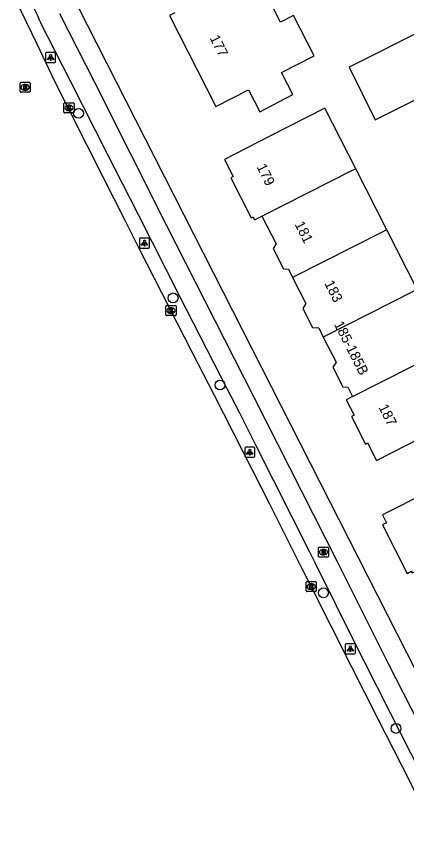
# Model space of a CAD drawing. Extents: x 162347 to 162868, y 381221 to 381813.
# Drawn here: x 162358.7 to 162397.4, y 381573.3 to 381653.9 of the extents above; entities that cross this region are included whole.
import ezdxf

# ---------------------------------------------------------------- set-up
doc = ezdxf.new("R2010")
doc.units = 0
for name, color, linetype in [('IMGEO_Boom', 7, 'Continuous'), ('IMGEO_Brandkraan', 7, 'Continuous'), ('IMGEO_Fietspad_open', 7, 'Continuous'), ('IMGEO_Kolk', 7, 'Continuous'), ('IMGEO_Lichtpunt', 7, 'Continuous'), ('IMGEO_Pand', 7, 'Continuous'), ('IMGEO_Pand_nummerreeks', 7, 'Continuous'), ('IMGEO_Rijbaan_regionaal_gesloten', 7, 'Continuous'), ('IMGEO_Rioolput', 7, 'Continuous'), ('IMGEO_Voetpad_open', 7, 'Continuous')]:
    doc.layers.add(name, color=color, linetype=linetype)

msp = doc.modelspace()

# ---------------------------------------------------------------- linework, layer by layer
at = {"layer": 'IMGEO_Boom'}
for centre in [(162364.839, 381644.26), (162374.24, 381625.935), (162378.89, 381617.287), (162389.173, 381596.654), (162396.379, 381583.19)]:
    msp.add_circle(centre, 0.489, dxfattribs=at)
at = {"layer": 'IMGEO_Brandkraan'}
for p, q in [((162388.675, 381600.263), (162388.675, 381601.115)), ((162388.75, 381601.189), (162389.602, 381601.189)), ((162389.163, 381600.969), (162389.188, 381600.969)), ((162389.676, 381601.115), (162389.676, 381600.263)), ((162389.602, 381600.189), (162388.75, 381600.189)), ((162389.186, 381600.409), (162389.161, 381600.409))]:
    msp.add_line(p, q, dxfattribs=at)
for points in [[(162388.675, 381600.263), (162388.675, 381601.115)], [(162388.75, 381601.189), (162389.602, 381601.189)], [(162389.023, 381600.889), (162389.023, 381600.489), (162389.236, 381600.489)], [(162389.254, 381600.889), (162389.023, 381600.889)], [(162389.202, 381600.808), (162389.148, 381600.808), (162389.148, 381600.732)], [(162389.676, 381601.115), (162389.676, 381600.263)], [(162389.602, 381600.189), (162388.75, 381600.189)], [(162389.148, 381600.732), (162389.201, 381600.732)], [(162389.21, 381600.656), (162389.148, 381600.656), (162389.148, 381600.575)], [(162389.148, 381600.575), (162389.21, 381600.575)]]:
    msp.add_lwpolyline(points, dxfattribs=at)
for centre, radius, start, end in [((162388.752, 381601.113), 0.0765, 91.55205, 178.44795), ((162388.752, 381601.113), 0.0765, 91.55205, 178.44795), ((162389.203, 381600.77), 0.0379, 267.82845, 90.93552), ((162389.258, 381600.744), 0.145, 59.4692, 91.53667), ((162389.283, 381600.791), 0.0922, 285.51372, 58.15012), ((162389.6, 381601.113), 0.0765, 1.55205, 88.44795), ((162389.6, 381601.113), 0.0765, 1.55205, 88.44795), ((162388.752, 381600.265), 0.0765, 181.55205, 268.44795), ((162388.752, 381600.265), 0.0765, 181.55205, 268.44795), ((162389.211, 381600.615), 0.0404, 269.87594, 90.50774), ((162389.242, 381600.74), 0.251, 268.66757, 293.53466), ((162389.288, 381600.599), 0.105, 301.31148, 78.98903), ((162389.6, 381600.265), 0.0765, 271.55205, 358.44795), ((162389.6, 381600.265), 0.0765, 271.55205, 358.44795)]:
    msp.add_arc(centre, radius, start, end, dxfattribs=at)
for centre, major_axis, ratio, start_param, end_param in [((162389.162, 381600.689), (-0.387, 0.002), 0.722429, 4.712389, 7.853982), ((162389.187, 381600.689), (-0.39, 0.002), 0.717154, 1.570796, 4.712389)]:
    msp.add_ellipse(centre, major_axis=major_axis, ratio=ratio, start_param=start_param, end_param=end_param, dxfattribs=at)
at = {"layer": 'IMGEO_Fietspad_open'}
for points in [[(162362.948, 381654.184), (162366.42, 381647.346), (162373.547, 381633.19), (162382.229, 381616.136), (162390.519, 381599.747), (162395.607, 381589.625), (162403.109, 381574.937), (162411.637, 381558.14), (162419.849, 381541.928), (162427.81, 381526.456), (162437.491, 381507.399), (162441.265, 381500), (162456.812, 381469.521), (162464.953, 381453.521)], [(162410.306, 381556.355), (162407.33, 381562.188), (162400.899, 381574.731), (162395.837, 381584.693), (162393.201, 381589.881), (162392.517, 381591.227), (162388.339, 381599.637), (162387.808, 381600.705), (162382.464, 381611.316), (162380.864, 381614.494), (162379.579, 381616.989), (162374.942, 381625.996), (162370.754, 381634.243), (162367.724, 381640.204), (162364.002, 381647.524), (162361.111, 381653.216)]]:
    msp.add_lwpolyline(points, dxfattribs=at)
msp.add_arc((162395.374, 381669.964), 38.137, 197.00448, 206.04996, dxfattribs=at)
at = {"layer": 'IMGEO_Kolk'}
for p, q in [((162363.394, 381644.371), (162363.394, 381645.223)), ((162363.469, 381645.297), (162364.321, 381645.297)), ((162364.395, 381645.223), (162364.395, 381644.371)), ((162364.321, 381644.297), (162363.469, 381644.297)), ((162363.905, 381644.517), (162363.88, 381644.517)), ((162363.882, 381645.077), (162363.907, 381645.077)), ((162373.529, 381624.247), (162373.529, 381625.099)), ((162373.604, 381625.173), (162374.456, 381625.173)), ((162374.017, 381624.953), (162374.042, 381624.953)), ((162374.53, 381625.099), (162374.53, 381624.247)), ((162374.456, 381624.173), (162373.604, 381624.173)), ((162374.04, 381624.393), (162374.015, 381624.393)), ((162387.453, 381596.844), (162387.453, 381597.696)), ((162387.528, 381597.77), (162388.38, 381597.77)), ((162388.454, 381597.696), (162388.454, 381596.844)), ((162388.38, 381596.77), (162387.528, 381596.77)), ((162387.964, 381596.99), (162387.939, 381596.99)), ((162387.941, 381597.55), (162387.966, 381597.55))]:
    msp.add_line(p, q, dxfattribs=at)
for points in [[(162363.394, 381644.371), (162363.394, 381645.223)], [(162363.469, 381645.297), (162364.321, 381645.297)], [(162364.395, 381645.223), (162364.395, 381644.371)], [(162364.321, 381644.297), (162363.469, 381644.297)], [(162363.715, 381644.997), (162363.838, 381644.997), (162363.838, 381644.846), (162363.968, 381644.997), (162364.132, 381644.997), (162363.986, 381644.846), (162364.139, 381644.597), (162363.987, 381644.597), (162363.902, 381644.761), (162363.838, 381644.694), (162363.838, 381644.597), (162363.715, 381644.597), (162363.715, 381644.997)], [(162373.529, 381624.247), (162373.529, 381625.099)], [(162373.604, 381625.173), (162374.456, 381625.173)], [(162374.53, 381625.099), (162374.53, 381624.247)], [(162374.456, 381624.173), (162373.604, 381624.173)], [(162373.85, 381624.873), (162373.973, 381624.873), (162373.973, 381624.722), (162374.103, 381624.873), (162374.267, 381624.873), (162374.121, 381624.722), (162374.274, 381624.473), (162374.122, 381624.473), (162374.037, 381624.637), (162373.973, 381624.57), (162373.973, 381624.473), (162373.85, 381624.473), (162373.85, 381624.873)], [(162387.453, 381596.844), (162387.453, 381597.696)], [(162387.528, 381597.77), (162388.38, 381597.77)], [(162388.454, 381597.696), (162388.454, 381596.844)], [(162388.38, 381596.77), (162387.528, 381596.77)], [(162387.774, 381597.47), (162387.897, 381597.47), (162387.897, 381597.319), (162388.027, 381597.47), (162388.191, 381597.47), (162388.045, 381597.319), (162388.198, 381597.07), (162388.046, 381597.07), (162387.961, 381597.234), (162387.897, 381597.167), (162387.897, 381597.07), (162387.774, 381597.07), (162387.774, 381597.47)]]:
    msp.add_lwpolyline(points, dxfattribs=at)
for centre, start, end in [((162363.471, 381645.221), 91.55205, 178.44795), ((162363.471, 381645.221), 91.55205, 178.44795), ((162364.319, 381645.221), 1.55205, 88.44795), ((162364.319, 381645.221), 1.55205, 88.44795), ((162363.471, 381644.373), 181.55205, 268.44795), ((162363.471, 381644.373), 181.55205, 268.44795), ((162364.319, 381644.373), 271.55205, 358.44795), ((162364.319, 381644.373), 271.55205, 358.44795), ((162373.606, 381625.097), 91.55205, 178.44795), ((162373.606, 381625.097), 91.55205, 178.44795), ((162374.454, 381625.097), 1.55205, 88.44795), ((162374.454, 381625.097), 1.55205, 88.44795), ((162373.606, 381624.249), 181.55205, 268.44795), ((162373.606, 381624.249), 181.55205, 268.44795), ((162374.454, 381624.249), 271.55205, 358.44795), ((162374.454, 381624.249), 271.55205, 358.44795), ((162387.53, 381597.694), 91.55205, 178.44795), ((162387.53, 381597.694), 91.55205, 178.44795), ((162388.378, 381597.694), 1.55205, 88.44795), ((162388.378, 381597.694), 1.55205, 88.44795), ((162387.53, 381596.846), 181.55205, 268.44795), ((162387.53, 381596.846), 181.55205, 268.44795), ((162388.378, 381596.846), 271.55205, 358.44795), ((162388.378, 381596.846), 271.55205, 358.44795)]:
    msp.add_arc(centre, 0.0765, start, end, dxfattribs=at)
for centre, major_axis, ratio, start_param, end_param in [((162363.881, 381644.797), (-0.387, 0.002), 0.722429, 4.712389, 7.853982), ((162363.906, 381644.797), (-0.39, 0.002), 0.717154, 1.570796, 4.712389), ((162374.016, 381624.673), (-0.387, 0.002), 0.722429, 4.712389, 7.853982), ((162374.041, 381624.673), (-0.39, 0.002), 0.717154, 1.570796, 4.712389), ((162387.94, 381597.27), (-0.387, 0.002), 0.722429, 4.712389, 7.853982), ((162387.965, 381597.27), (-0.39, 0.002), 0.717154, 1.570796, 4.712389)]:
    msp.add_ellipse(centre, major_axis=major_axis, ratio=ratio, start_param=start_param, end_param=end_param, dxfattribs=at)
at = {"layer": 'IMGEO_Lichtpunt'}
for p, q in [((162361.573, 381650.212), (162361.573, 381649.405)), ((162361.573, 381650.212), (162361.573, 381649.405)), ((162362.475, 381650.307), (162361.667, 381650.307)), ((162362.475, 381650.307), (162361.667, 381650.307)), ((162362.569, 381649.405), (162362.569, 381650.212)), ((162362.569, 381649.405), (162362.569, 381650.212)), ((162361.667, 381649.311), (162362.475, 381649.311)), ((162361.667, 381649.311), (162362.475, 381649.311)), ((162370.892, 381631.786), (162370.892, 381630.979)), ((162370.892, 381631.786), (162370.892, 381630.979)), ((162371.794, 381631.881), (162370.986, 381631.881)), ((162371.794, 381631.881), (162370.986, 381631.881)), ((162371.888, 381630.979), (162371.888, 381631.786)), ((162371.888, 381630.979), (162371.888, 381631.786)), ((162370.986, 381630.885), (162371.794, 381630.885)), ((162370.986, 381630.885), (162371.794, 381630.885)), ((162381.356, 381611.024), (162381.356, 381610.217)), ((162381.356, 381611.024), (162381.356, 381610.217)), ((162382.258, 381611.119), (162381.45, 381611.119)), ((162382.258, 381611.119), (162381.45, 381611.119)), ((162382.352, 381610.217), (162382.352, 381611.024)), ((162382.352, 381610.217), (162382.352, 381611.024)), ((162381.45, 381610.123), (162382.258, 381610.123)), ((162381.45, 381610.123), (162382.258, 381610.123)), ((162391.346, 381591.494), (162391.346, 381590.687)), ((162391.346, 381591.494), (162391.346, 381590.687)), ((162392.248, 381591.589), (162391.44, 381591.589)), ((162392.248, 381591.589), (162391.44, 381591.589)), ((162392.342, 381590.687), (162392.342, 381591.494)), ((162392.342, 381590.687), (162392.342, 381591.494)), ((162391.44, 381590.593), (162392.248, 381590.593)), ((162391.44, 381590.593), (162392.248, 381590.593))]:
    msp.add_line(p, q, dxfattribs=at)
for points in [[(162361.947, 381649.876), (162361.986, 381649.848), (162361.798, 381649.586), (162361.76, 381649.613), (162361.947, 381649.876)], [(162362.049, 381649.828), (162362.096, 381649.828), (162362.096, 381649.506), (162362.049, 381649.506), (162362.049, 381649.828)], [(162362.159, 381649.848), (162362.197, 381649.875), (162362.384, 381649.613), (162362.345, 381649.585), (162362.159, 381649.848)], [(162371.266, 381631.45), (162371.305, 381631.422), (162371.117, 381631.16), (162371.079, 381631.187), (162371.266, 381631.45)], [(162371.368, 381631.402), (162371.415, 381631.402), (162371.415, 381631.08), (162371.368, 381631.08), (162371.368, 381631.402)], [(162371.478, 381631.422), (162371.516, 381631.449), (162371.703, 381631.187), (162371.664, 381631.159), (162371.478, 381631.422)], [(162381.73, 381610.688), (162381.769, 381610.66), (162381.581, 381610.398), (162381.543, 381610.425), (162381.73, 381610.688)], [(162381.832, 381610.64), (162381.879, 381610.64), (162381.879, 381610.318), (162381.832, 381610.318), (162381.832, 381610.64)], [(162381.942, 381610.66), (162381.98, 381610.687), (162382.167, 381610.425), (162382.128, 381610.397), (162381.942, 381610.66)], [(162391.72, 381591.158), (162391.759, 381591.13), (162391.571, 381590.868), (162391.533, 381590.895), (162391.72, 381591.158)], [(162391.822, 381591.11), (162391.869, 381591.11), (162391.869, 381590.788), (162391.822, 381590.788), (162391.822, 381591.11)], [(162391.932, 381591.13), (162391.97, 381591.157), (162392.157, 381590.895), (162392.118, 381590.867), (162391.932, 381591.13)]]:
    msp.add_lwpolyline(points, dxfattribs=at)
for centre in [(162362.072, 381650.01), (162371.391, 381631.584), (162381.855, 381610.822), (162391.845, 381591.292)]:
    msp.add_circle(centre, 0.0994, dxfattribs=at)
for centre, start, end in [((162361.667, 381650.212), 90, 180), ((162361.667, 381650.212), 90, 180), ((162362.475, 381650.212), 0, 90), ((162362.475, 381650.212), 0, 90), ((162361.667, 381649.405), 180, 270), ((162361.667, 381649.405), 180, 270), ((162362.475, 381649.405), 270, 0), ((162362.475, 381649.405), 270, 360), ((162370.986, 381631.786), 90, 180), ((162370.986, 381631.786), 90, 180), ((162371.794, 381631.786), 0, 90), ((162371.794, 381631.786), 0, 90), ((162370.986, 381630.979), 180, 270), ((162370.986, 381630.979), 180, 270), ((162371.794, 381630.979), 270, 0), ((162371.794, 381630.979), 270, 360), ((162381.45, 381611.024), 90, 180), ((162381.45, 381611.024), 90, 180), ((162382.258, 381611.024), 0, 90), ((162382.258, 381611.024), 0, 90), ((162381.45, 381610.217), 180, 270), ((162381.45, 381610.217), 180, 270), ((162382.258, 381610.217), 270, 0), ((162382.258, 381610.217), 270, 360), ((162391.44, 381591.494), 90, 180), ((162391.44, 381591.494), 90, 180), ((162392.248, 381591.494), 0, 90), ((162392.248, 381591.494), 0, 90), ((162391.44, 381590.687), 180, 270), ((162391.44, 381590.687), 180, 270), ((162392.248, 381590.687), 270, 0), ((162392.248, 381590.687), 270, 360)]:
    msp.add_arc(centre, 0.0946, start, end, dxfattribs=at)
at = {"layer": 'IMGEO_Pand'}
for points in [[(162374.408, 381654.239), (162373.886, 381653.972), (162378.488, 381644.927), (162381.742, 381646.582), (162382.855, 381644.417), (162386.146, 381646.123), (162385.019, 381648.298), (162388.244, 381649.97), (162386.203, 381653.979), (162384.898, 381653.315), (162384.079, 381654.925), (162388.651, 381657.252), (162387.852, 381658.821), (162386.481, 381661.514), (162384.132, 381660.319)], [(162399.713, 381652.851), (162391.711, 381648.827), (162394.326, 381643.627), (162402.34, 381647.657)], [(162392.382, 381638.757), (162389.324, 381644.767), (162383.789, 381641.951), (162379.332, 381639.684), (162380.199, 381637.98), (162379.965, 381637.861), (162381.993, 381633.874), (162382.175, 381633.967), (162382.323, 381633.676), (162383.063, 381634.048)], [(162383.063, 381634.048), (162392.066, 381638.601), (162392.382, 381638.757)], [(162395.465, 381632.697), (162392.382, 381638.757)], [(162383.063, 381634.048), (162384.46, 381631.302), (162384.164, 381630.847), (162385.199, 381628.813), (162385.688, 381628.787), (162386.11, 381627.958)], [(162395.465, 381632.697), (162395.139, 381632.524), (162386.11, 381627.958)], [(162398.481, 381626.77), (162395.465, 381632.697)], [(162386.11, 381627.958), (162387.426, 381625.372), (162387.118, 381624.899), (162388.095, 381622.98), (162388.7, 381622.947), (162389.157, 381622.048)], [(162398.481, 381626.77), (162398.14, 381626.591), (162389.157, 381622.048)], [(162389.157, 381622.048), (162390.426, 381619.555), (162390.098, 381619.05), (162391.087, 381617.106), (162391.598, 381617.079), (162392.072, 381616.147)], [(162392.072, 381616.147), (162391.431, 381615.821), (162392.214, 381614.28), (162391.947, 381614.144), (162393.333, 381611.419), (162393.56, 381611.534), (162394.445, 381609.794), (162398.902, 381612.062), (162404.512, 381614.916), (162401.468, 381620.899)], [(162392.072, 381616.147), (162401.111, 381620.715), (162401.468, 381620.899)], [(162408.169, 381603.815), (162408.091, 381603.968), (162407.93, 381604.285), (162406.673, 381606.755), (162409.231, 381608.056), (162407.798, 381610.873), (162399.497, 381606.65), (162395.04, 381604.382), (162395.432, 381603.613), (162395.031, 381603.409), (162397.484, 381598.588), (162397.885, 381598.792), (162397.971, 381598.622), (162398.225, 381598.75)]]:
    msp.add_lwpolyline(points, dxfattribs=at)
at = {"layer": 'IMGEO_Rijbaan_regionaal_gesloten'}
msp.add_lwpolyline([(162409.049, 381555.709), (162408.71, 381556.396), (162406.049, 381561.587), (162402.557, 381568.4), (162396.915, 381579.56), (162394.619, 381584.098), (162391.996, 381589.28), (162387.783, 381597.606), (162387.066, 381599.034), (162383.842, 381605.454), (162381.2, 381610.636), (162378.309, 381616.304), (162376.144, 381620.551), (162370.915, 381630.775), (162369.471, 381633.629), (162367.291, 381637.935), (162362.48, 381647.434), (162360.733, 381651.139), (162358.654, 381655.431)], dxfattribs=at)
at = {"layer": 'IMGEO_Rioolput'}
for p, q in [((162359.041, 381646.419), (162359.041, 381647.271)), ((162359.116, 381647.345), (162359.968, 381647.345)), ((162359.529, 381647.125), (162359.554, 381647.125)), ((162360.042, 381647.271), (162360.042, 381646.419)), ((162359.968, 381646.345), (162359.116, 381646.345)), ((162359.552, 381646.565), (162359.527, 381646.565))]:
    msp.add_line(p, q, dxfattribs=at)
for points in [[(162359.041, 381646.419), (162359.041, 381647.271)], [(162359.116, 381647.345), (162359.968, 381647.345)], [(162359.63, 381647.043), (162359.378, 381647.045), (162359.378, 381646.645)], [(162359.378, 381646.645), (162359.502, 381646.645), (162359.502, 381646.807), (162359.513, 381646.807)], [(162359.556, 381646.964), (162359.502, 381646.964), (162359.502, 381646.883)], [(162359.502, 381646.883), (162359.554, 381646.883)], [(162359.56, 381646.778), (162359.631, 381646.645), (162359.771, 381646.645), (162359.706, 381646.771)], [(162360.042, 381647.271), (162360.042, 381646.419)], [(162359.968, 381646.345), (162359.116, 381646.345)]]:
    msp.add_lwpolyline(points, dxfattribs=at)
for centre, radius, start, end in [((162359.118, 381647.269), 0.0765, 91.55205, 178.44795), ((162359.118, 381647.269), 0.0765, 91.55205, 178.44795), ((162359.512, 381646.754), 0.0533, 26.02933, 88.69889), ((162359.538, 381647.072), 0.19, 274.7715, 282.96867), ((162359.562, 381646.868), 0.0964, 77.00612, 93.18647), ((162359.576, 381646.925), 0.0378, 276.66336, 79.67722), ((162359.629, 381646.933), 0.109, 350.36119, 89.41601), ((162359.627, 381646.933), 0.112, 277.58423, 350.98172), ((162359.611, 381646.718), 0.108, 29.51342, 73.79051), ((162359.966, 381647.269), 0.0765, 1.55205, 88.44795), ((162359.966, 381647.269), 0.0765, 1.55205, 88.44795), ((162359.118, 381646.421), 0.0765, 181.55205, 268.44795), ((162359.118, 381646.421), 0.0765, 181.55205, 268.44795), ((162359.966, 381646.421), 0.0765, 271.55205, 358.44795), ((162359.966, 381646.421), 0.0765, 271.55205, 358.44795)]:
    msp.add_arc(centre, radius, start, end, dxfattribs=at)
for centre, major_axis, ratio, start_param, end_param in [((162359.528, 381646.845), (-0.387, 0.002), 0.722429, 4.712389, 7.853982), ((162359.553, 381646.845), (-0.39, 0.002), 0.717154, 1.570796, 4.712389)]:
    msp.add_ellipse(centre, major_axis=major_axis, ratio=ratio, start_param=start_param, end_param=end_param, dxfattribs=at)
at = {"layer": 'IMGEO_Voetpad_open'}
msp.add_lwpolyline([(162466.79, 381454.429), (162443.597, 381500), (162364.764, 381654.894)], dxfattribs=at)

# ---------------------------------------------------------------- texts
at = {"layer": 'IMGEO_Pand_nummerreeks'}
for s, rotation, p in [('177', 296.96891, (162377.85, 381651.741)), ('179', 296.46579, (162382.51, 381638.955)), ('181', 296.71461, (162386.286, 381633.249)), ('183', 296.71461, (162389.239, 381627.382)), ('185-185B', 296.97464, (162390.189, 381623.328)), ('187', 296.56885, (162394.616, 381615.087))]:
    msp.add_text(s, height=1, rotation=rotation, dxfattribs=at).set_placement(p)

doc.saveas('drawing.dxf')
